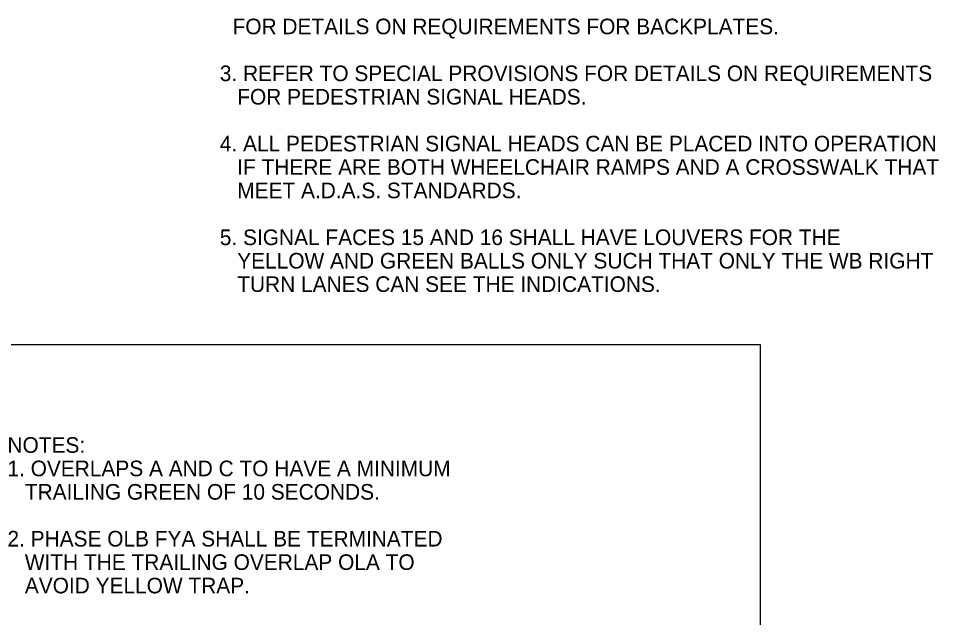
# Model space of a CAD drawing. Extents: x -218554 to 420030, y -565899 to -483460.
# Drawn here: x 419024.1 to 419259.9, y -565580.9 to -565427.4 of the extents above; entities that cross this region are included whole.
import ezdxf

# ---------------------------------------------------------------- set-up
doc = ezdxf.new("R2010")
doc.units = 0
doc.layers.add('T_Notes', color=7, linetype='Continuous')
doc.layers.add('Template', color=7, linetype='Continuous')

msp = doc.modelspace()

# ---------------------------------------------------------------- linework, layer by layer
at = {"layer": 'Template'}
msp.add_lwpolyline([(419214.2, -565511.02), (418906.32, -565511.02), (418906.32, -565641.34), (419214.2, -565641.34)], close=True, dxfattribs=at)

# ---------------------------------------------------------------- texts
at = {"layer": 'T_Notes'}
for s, p in [('   FOR DETAILS ON REQUIREMENTS FOR BACKPLATES.', (419074.52, -565431.48)), ('3. REFER TO SPECIAL PROVISIONS FOR DETAILS ON REQUIREMENTS', (419075.72, -565443.48)), ('   FOR PEDESTRIAN SIGNAL HEADS.', (419075.72, -565449.48)), ('4. ALL PEDESTRIAN SIGNAL HEADS CAN BE PLACED INTO OPERATION', (419075.72, -565461.48)), ('   IF THERE ARE BOTH WHEELCHAIR RAMPS AND A CROSSWALK THAT', (419075.72, -565467.48)), ('   MEET A.D.A.S. STANDARDS.', (419075.72, -565473.48)), ('5. SIGNAL FACES 15 AND 16 SHALL HAVE LOUVERS FOR THE', (419075.72, -565485.48)), ('   YELLOW AND GREEN BALLS ONLY SUCH THAT ONLY THE WB RIGHT', (419075.72, -565491.48)), ('   TURN LANES CAN SEE THE INDICATIONS.', (419075.72, -565497.48)), ('NOTES:', (419021.31, -565538.68)), ('1. OVERLAPS A AND C TO HAVE A MINIMUM', (419021.31, -565544.68)), ('   TRAILING GREEN OF 10 SECONDS.', (419021.31, -565550.68)), ('2. PHASE OLB FYA SHALL BE TERMINATED', (419021.31, -565562.68)), ('   WITH THE TRAILING OVERLAP OLA TO', (419021.31, -565568.68)), ('   AVOID YELLOW TRAP.', (419021.31, -565574.68))]:
    msp.add_text(s, height=4, dxfattribs=at).set_placement(p)

doc.saveas('drawing.dxf')
